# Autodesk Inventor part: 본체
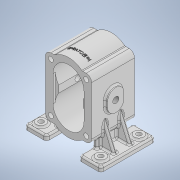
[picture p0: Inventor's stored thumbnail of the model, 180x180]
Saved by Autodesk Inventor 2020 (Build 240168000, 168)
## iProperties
Created: 2023-06
Part Number: 본체
Material: 일반
Document SubType Name: Modeling
Designer: oem
Density: 1 g/cm^3
Appearance: 기본값
Author: oem
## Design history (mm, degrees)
sketch "스케치1"
  geometry: L1 (42.5, -55)-(-42.5, -55); L2 (-42.5, -55)-(-42.5, 55); L3 (-42.5, 55)-(42.5, 55); L4 (42.5, 55)-(42.5, -55); L5 (42.5, -55)-(-42.5, 55); L6 (-42.5, -55)-(42.5, 55); 1 further point
  constraints: 12 end point, 2 midpoint, 2 parallel, 1 horizontal, 1 perpendicular
  dimensions: "d0" = 85 distance of L2.end L3.end; "d1" = 110 distance of L1.end L2.end
extrude "돌출1" new body sketch "스케치1" stored distance "d2" = 79; taper "d3" = 0 deg
fillet "모깎기1" dims "d4" = 10
sketch "스케치3"
  geometry: L1 (-32.5, 55)-(32.5, 55) reference; L2 (0, 55)-(0, -55); L3 (32.5, -55)-(-32.5, -55) reference; C1 r 40 at (0, 24); C2 r 40 at (0, -24); 3 further points
  constraints: 3 midpoint, 2 centre point, 2 end point, 2 point on line
  dimensions: "d9" = 80 diameter of C1; "d13" = 24 distance of point (0, 0) C1.centre; "d14" = 80 diameter of C2; "d15" = 24 distance of point (0, 0) C2.centre; "d16" = 55 distance from line of L1 point (0, 0)
extrude "돌출3" join sketch "스케치3" stored distance "d11" = 79; taper "d12" = 0 deg
sketch "스케치5"
  geometry: L1 (-22.5, -10)-(22.5, -10); L2 (22.5, -10)-(22.5, 10); L3 (22.5, 10)-(-22.5, 10); L4 (-22.5, 10)-(-22.5, -10); L5 (-22.5, -10)-(22.5, 10); L6 (22.5, -10)-(-22.5, 10); C1 r 28.5 at (0, 24); C2 r 28.5 at (0, -24); 7 further points
  constraints: 12 end point, 2 centre point, 2 midpoint, 2 parallel, 2 vertical alignment, 1 horizontal, 1 perpendicular
  dimensions: "d17" = 57 diameter of C1; "d18" = 24 distance of point (0, 0) C1.centre; "d19" = 57 diameter of C2; "d20" = 24 distance of C2.centre point (0, 0); "d25" = 45 distance of L3.end L2.end; "d26" = 20 distance of L2.end L1.end
extrude "돌출4" cut sketch "스케치5" stored distance "d21" = 79; taper "d22" = 0 deg
sketch "스케치6"
  geometry: L1 (-28.5, 24)-(-28.5, -24); L2 (-28.5, 24)-(28.5, 24); L3 (28.5, -24)-(28.5, 24); L4 (28.5, -24)-(-28.5, -24); A1 r 28.5 centre (0, 24) between (22.5, 6.507) and (-22.5, 6.507) reference; A2 r 28.5 centre (0, -24) between (-22.5, -6.507) and (22.5, -6.507) reference; 3 further points
  constraints: 8 end point, 4 point on circle, 3 tangent, 2 horizontal, 1 perpendicular
extrude "돌출5" cut sketch "스케치6" distance "d23" = 4.5; taper "d24" = 0 deg
fillet "모깎기3" dims "d27" = 3
sketch "스케치7"
  geometry: L1 (-54.5, 50)-(-24.5, 50); L2 (-24.5, 50)-(-24.5, 40); L3 (-24.5, 40)-(-54.5, 40); L4 (-54.5, 40)-(-54.5, 50); L5 (-54.5, 50)-(-24.5, 40); L6 (-24.5, 50)-(-54.5, 40); A1 r 15 centre (-39.5, 50) between (-24.5, 50) and (-54.5, 50); A2 r 15 centre (-39.5, 40) between (-54.5, 40) and (-24.5, 40); 1 further point
  constraints: 12 end point, 4 midpoint, 4 point on circle, 2 centre point, 2 parallel, 1 horizontal, 1 perpendicular
  dimensions: "d28" = 30 distance of L2.end L3.end; "d29" = 10 distance of L1.end L2.end
extrude "돌출6" join sketch "스케치7" distance "d30" = 5; taper "d31" = 0 deg
fillet "모깎기4" dims "d32" = 3
sketch "스케치8"
  geometry: 2 further points
  constraints: 1 coincident
hole "구멍1" sketch "스케치8" at (-39.5, 45) diameter "d33" = 10.5; stored, may be unused: countersink angle "d39" = 90 deg, drill point angle "d41" = 0 deg; dims "d34" = 11, "d35" = 0.62479, "d36" = 10.589, "d37" = 4, "d38" = 2, "d40" = 17.5
node "작업 평면1"
sketch "스케치9"
  geometry: L1 (70, -50)-(30, -50); L2 (30, -50)-(30, 50); L3 (30, 50)-(70, 50); L4 (70, 50)-(70, -50); L5 (70, -50)-(30, 50); L6 (30, -50)-(70, 50); L7 (-30, 50)-(-70, 50); L8 (-70, 50)-(-70, -50); L9 (-70, -50)-(-30, -50); L10 (-30, -50)-(-30, 50); L11 (-30, 50)-(-70, -50); L12 (-70, 50)-(-30, -50); 3 further points
  constraints: 24 end point, 4 midpoint, 4 parallel, 2 horizontal, 2 perpendicular
  dimensions: "d43" = 40 distance of L2.end L3.end; "d44" = 100 distance of L1.end L2.end; "d45" = 70 distance from line of point (0, 0) L4; "d46" = 50 distance from line of point (0, 0) L1; "d47" = 40 distance of L9.end L8.end; "d48" = 100 distance of L8.end L7.end; "d49" = 70 distance from line of L8 point (0, 0); "d50" = 50 distance from line of L9 point (0, 0)
extrude "돌출7" join sketch "스케치9" distance "d51" = 9; taper "d52" = 0 deg
sketch "스케치10"
  geometry: L1 (30, 50)-(30, -50) reference; L2 (-30, -50)-(-30, 50) reference; L3 (-30, 0)-(-30, 25); L4 (-30, 25)-(-38, 25); L5 (-38, 25)-(-38, -25); L6 (-38, -25)-(-30, -25); L7 (-30, -25)-(-30, 0); L8 (0, -39.136)-(0, 36.284); L9 (30, 25)-(38, 25); L10 (38, 25)-(38, -25); L11 (38, -25)-(30, -25); L12 (30, 25)-(30, -25); L13 (30, 50)-(30, -50) reference; 3 further points
  constraints: 20 end point, 4 symmetric about line, 3 point on line, 2 collinear, 1 horizontal, 1 midpoint, 1 parallel, 1 vertical
  dimensions: "d53" = 25 distance of L3.start L3.end; "d54" = 8 distance of L3.end L4.end; "d55" = 50 distance of L4.end L5.end; "d56" = 8 distance of L5.end L6.end
extrude "돌출8" join sketch "스케치10" distance "d57" = 30; taper "d58" = 0 deg
node "작업 평면2"
sketch "스케치11"
  geometry: L1 (42.5, -25.061)-(62, -71); L2 (70, -71)-(30, -71) reference; L3 (70, -80)-(70, -71) reference; L4 (42.5, 45)-(42.5, -45) reference; 1 further point
  constraints: 2 end point, 2 point on line
  dimensions: "d60" = 8 distance of L2.start L1.end; "d61" = 23 deg angle of L3 L1
feature "리브1" sketch "스케치11" dims "d62" = 1, "d63" = 7, "d64" = 0, "d65" = 0, "d66" = 1, "d67" = 1
fillet "모깎기5" dims "d68" = 5
node "작업 평면4"
sketch "스케치12"
  geometry: C1 r 9 at (-55, -35); 1 further point
  constraints: 1 centre point
  dimensions: "d71" = 18 diameter of C1; "d72" = 55 horizontal distance of C1.centre point (0, 0); "d73" = 35 vertical distance of C1.centre point (0, 0)
extrude "돌출9" join sketch "스케치12" distance "d74" = 3; taper "d75" = 0 deg
sketch "스케치13"
  geometry: C1 r 9 at (0, 0) reference; 2 further points
  constraints: 1 coincident
hole "구멍2" sketch "스케치13" at (0, 0) diameter "d82" = 9; stored, may be unused: countersink angle "d86" = 90 deg, drill point angle "d88" = 0 deg; dims "d83" = 11, "d84" = 4, "d85" = 2, "d87" = 17.5
fillet "모깎기7" dims "d95" = 3
fillet "모깎기8" dims "d96" = 3
fillet "모깎기9" dims "d97" = 3
fillet "모깎기10" dims "d98" = 3
fillet "모깎기11" dims "d99" = 3
sketch "스케치14"
  geometry: C1 r 4.5 at (32.5, 45); 1 further point
  constraints: 1 centre point
  dimensions: "d100" = 9 diameter of C1; "d101" = 32.5 horizontal distance of point (0, 0) C1.centre; "d102" = 45 vertical distance of C1.centre point (0, 0)
extrude "돌출10" cut sketch "스케치14" stored distance "d103" = 3; taper "d104" = 0 deg
node "작업 평면5"
sketch "스케치15"
  geometry: 2 further points
  constraints: 1 vertical alignment, 1 other
  dimensions: "d112" = 20 distance of point (0, 20) point (0, 0)
feature "엠보싱1" sketch "스케치15" dims "d9" = 80, "d13" = 24, "d14" = 80, "d15" = 24, "d16" = 55, "d113" = 0.5, "d114" = 0
fillet "모깎기12" dims "d115" = 3
node "솔리드1"
mirror "미러1"
mirror "미러2"
mirror "미러3"
mirror "미러4"
mirror "미러5"
pattern_linear "직사각형 패턴1" dims "d78" = 70, "d81" = 110
pattern_linear "직사각형 패턴2" dims "d91" = 70, "d94" = 110
pattern_linear "직사각형 패턴3" dims "d107" = 90, "d110" = 65
feature "A9D066F2-1C7D-4E18-AEED-F7BC21143FA4" dims "d33" = 10.5, "d34" = 11, "d35" = 0.62479, "d36" = 10.589, "d37" = 4, "d38" = 2, "d39" = 90 deg, "d40" = 17.5, "d41" = 0
other parameters: "d59" = 14.5, "d111" = 119
